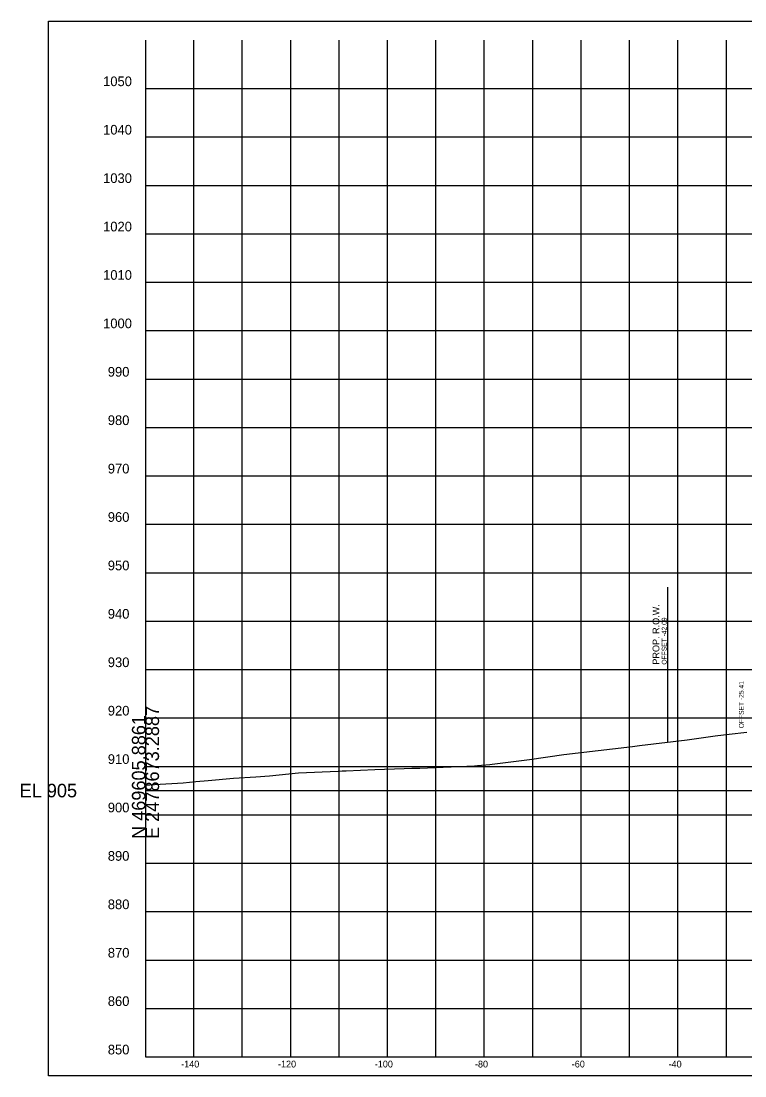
# Model space of a CAD drawing. Extents: x -26 to 2478923, y -10 to 469990.
# Drawn here: x -25.7 to 123.8, y 5941.1 to 6158.9 of the extents above; entities that cross this region are included whole.
import ezdxf

# ---------------------------------------------------------------- set-up
doc = ezdxf.new("R2010")
doc.units = 0
for name, color, linetype in [('DESIGN - ROW - Right-of-Way and Easement Labels', 7, 'Continuous'), ('DESIGN - ROW - Right-of-Way Linework', 7, 'Continuous'), ('DESIGN - SHEET - Corner Text', 7, 'Continuous'), ('DESIGN - SHEET - Light Grid', 7, 'Continuous'), ('DESIGN - SHEET - Linework', 7, 'Continuous'), ('DESIGN - SHEET - Plot Shape', 7, 'Continuous'), ('DESIGN - TYPICAL - Slope Tie Text', 7, 'Continuous'), ('SURVEY - GROUND - Top of Ground', 7, 'Continuous')]:
    doc.layers.add(name, color=color, linetype=linetype)

msp = doc.modelspace()

# ---------------------------------------------------------------- linework, layer by layer
at = {"layer": 'DESIGN - ROW - Right-of-Way Linework'}
msp.add_line((107.91, 6010.01), (107.91, 6042.01), dxfattribs=at)
at = {"layer": 'DESIGN - SHEET - Light Grid'}
msp.add_line((0, 6000), (150, 6000), dxfattribs=at)
at = {"layer": 'DESIGN - SHEET - Linework'}
for p, q in [((10, 5945), (10, 6155)), ((10, 5945), (10, 6155)), ((10, 5945), (10, 6155)), ((10, 5945), (10, 6155)), ((20, 5945), (20, 6155)), ((20, 5945), (20, 6155)), ((20, 5945), (20, 6155)), ((20, 5945), (20, 6155)), ((30, 5945), (30, 6155)), ((30, 5945), (30, 6155)), ((30, 5945), (30, 6155)), ((30, 5945), (30, 6155)), ((40, 5945), (40, 6155)), ((40, 5945), (40, 6155)), ((40, 5945), (40, 6155)), ((40, 5945), (40, 6155)), ((50, 5945), (50, 6155)), ((50, 5945), (50, 6155)), ((50, 5945), (50, 6155)), ((50, 5945), (50, 6155)), ((60, 5945), (60, 6155)), ((60, 5945), (60, 6155)), ((60, 5945), (60, 6155)), ((60, 5945), (60, 6155)), ((70, 5945), (70, 6155)), ((70, 5945), (70, 6155)), ((70, 5945), (70, 6155)), ((70, 5945), (70, 6155)), ((80, 5945), (80, 6155)), ((80, 5945), (80, 6155)), ((80, 5945), (80, 6155)), ((80, 5945), (80, 6155)), ((90, 5945), (90, 6155)), ((90, 5945), (90, 6155)), ((90, 5945), (90, 6155)), ((90, 5945), (90, 6155)), ((100, 5945), (100, 6155)), ((100, 5945), (100, 6155)), ((100, 5945), (100, 6155)), ((100, 5945), (100, 6155)), ((110, 5945), (110, 6155)), ((110, 5945), (110, 6155)), ((110, 5945), (110, 6155)), ((110, 5945), (110, 6155)), ((120, 5945), (120, 6155)), ((120, 5945), (120, 6155)), ((120, 5945), (120, 6155)), ((120, 5945), (120, 6155)), ((0, 6145), (300, 6145)), ((0, 6145), (300, 6145)), ((0, 6145), (300, 6145)), ((0, 6145), (300, 6145)), ((0, 6135), (300, 6135)), ((0, 6135), (300, 6135)), ((0, 6135), (300, 6135)), ((0, 6135), (300, 6135)), ((0, 6125), (300, 6125)), ((0, 6125), (300, 6125)), ((0, 6125), (300, 6125)), ((0, 6125), (300, 6125)), ((0, 6115), (300, 6115)), ((0, 6115), (300, 6115)), ((0, 6115), (300, 6115)), ((0, 6115), (300, 6115)), ((0, 6105), (300, 6105)), ((0, 6105), (300, 6105)), ((0, 6105), (300, 6105)), ((0, 6105), (300, 6105)), ((0, 6095), (300, 6095)), ((0, 6095), (300, 6095)), ((0, 6095), (300, 6095)), ((0, 6095), (300, 6095)), ((0, 6085), (300, 6085)), ((0, 6085), (300, 6085)), ((0, 6085), (300, 6085)), ((0, 6085), (300, 6085)), ((0, 6075), (300, 6075)), ((0, 6075), (300, 6075)), ((0, 6075), (300, 6075)), ((0, 6075), (300, 6075)), ((0, 6065), (300, 6065)), ((0, 6065), (300, 6065)), ((0, 6065), (300, 6065)), ((0, 6065), (300, 6065)), ((0, 6055), (300, 6055)), ((0, 6055), (300, 6055)), ((0, 6055), (300, 6055)), ((0, 6055), (300, 6055)), ((0, 6045), (300, 6045)), ((0, 6045), (300, 6045)), ((0, 6045), (300, 6045)), ((0, 6045), (300, 6045)), ((0, 6035), (300, 6035)), ((0, 6035), (300, 6035)), ((0, 6035), (300, 6035)), ((0, 6035), (300, 6035)), ((0, 6025), (300, 6025)), ((0, 6025), (300, 6025)), ((0, 6025), (300, 6025)), ((0, 6025), (300, 6025)), ((0, 6015), (300, 6015)), ((0, 6015), (300, 6015)), ((0, 6015), (300, 6015)), ((0, 6015), (300, 6015)), ((0, 6005), (300, 6005)), ((0, 6005), (300, 6005)), ((0, 6005), (300, 6005)), ((0, 6005), (300, 6005)), ((0, 5995), (300, 5995)), ((0, 5995), (300, 5995)), ((0, 5995), (300, 5995)), ((0, 5995), (300, 5995)), ((0, 5985), (300, 5985)), ((0, 5985), (300, 5985)), ((0, 5985), (300, 5985)), ((0, 5985), (300, 5985)), ((0, 5975), (300, 5975)), ((0, 5975), (300, 5975)), ((0, 5975), (300, 5975)), ((0, 5975), (300, 5975)), ((0, 5965), (300, 5965)), ((0, 5965), (300, 5965)), ((0, 5965), (300, 5965)), ((0, 5965), (300, 5965)), ((0, 5955), (300, 5955)), ((0, 5955), (300, 5955)), ((0, 5955), (300, 5955)), ((0, 5955), (300, 5955))]:
    msp.add_line(p, q, dxfattribs=at)
msp.add_lwpolyline([(0, 6155), (0, 5945), (300, 5945), (300, 6155)], dxfattribs=at)
msp.add_lwpolyline([(0, 6155), (0, 5945), (300, 5945), (300, 6155)], dxfattribs=at)
msp.add_lwpolyline([(0, 6155), (0, 5945), (300, 5945), (300, 6155)], dxfattribs=at)
msp.add_lwpolyline([(0, 6155), (0, 5945), (300, 5945), (300, 6155)], dxfattribs=at)
at = {"layer": 'DESIGN - SHEET - Plot Shape'}
msp.add_lwpolyline([(-20, 6158.94), (320, 6158.94), (320, 5941.06), (-20, 5941.06)], close=True, dxfattribs=at)
msp.add_lwpolyline([(-20, 6158.94), (320, 6158.94), (320, 5941.06), (-20, 5941.06)], close=True, dxfattribs=at)
msp.add_lwpolyline([(-20, 6158.94), (320, 6158.94), (320, 5941.06), (-20, 5941.06)], close=True, dxfattribs=at)
msp.add_lwpolyline([(-20, 6158.94), (320, 6158.94), (320, 5941.06), (-20, 5941.06)], close=True, dxfattribs=at)
at = {"layer": 'SURVEY - GROUND - Top of Ground'}
msp.add_lwpolyline([(0, 6001.09), (1.85, 6001.23), (7.78, 6001.61), (10.41, 6001.88), (12.95, 6002.05), (18.2, 6002.55), (22.78, 6002.81), (25.64, 6003.03), (31.6, 6003.66), (39.78, 6004), (40.66, 6004.05), (41.44, 6004.05), (47.38, 6004.35), (53.43, 6004.56), (55.02, 6004.63), (56.71, 6004.64), (67.96, 6005.13), (68.58, 6005.2), (71.17, 6005.38), (71.64, 6005.42), (79.32, 6006.4), (86.44, 6007.46), (89.39, 6007.81), (100.58, 6009.1), (101.11, 6009.17), (102.04, 6009.29), (111.9, 6010.51), (117.71, 6011.32), (120.57, 6011.65), (124.24, 6012.06)], dxfattribs=at)

# ---------------------------------------------------------------- texts
at = {"layer": 'DESIGN - ROW - Right-of-Way and Easement Labels'}
for s, height, p in [('PROP. R.O.W.', 1.4, (106.16, 6026.01)), ('OFFSET -42.09', 1, (107.66, 6026.01))]:
    msp.add_text(s, height=height, rotation=90, dxfattribs=at).set_placement(p)
at = {"layer": 'DESIGN - SHEET - Corner Text'}
for s, height, p in [('1050', 2, (-8.75, 6145.5)), ('1050', 2, (-8.75, 6145.5)), ('1050', 2, (-8.75, 6145.5)), ('1050', 2, (-8.75, 6145.5)), ('1040', 2, (-8.75, 6135.5)), ('1040', 2, (-8.75, 6135.5)), ('1040', 2, (-8.75, 6135.5)), ('1040', 2, (-8.75, 6135.5)), ('1030', 2, (-8.75, 6125.5)), ('1030', 2, (-8.75, 6125.5)), ('1030', 2, (-8.75, 6125.5)), ('1030', 2, (-8.75, 6125.5)), ('1020', 2, (-8.75, 6115.5)), ('1020', 2, (-8.75, 6115.5)), ('1020', 2, (-8.75, 6115.5)), ('1020', 2, (-8.75, 6115.5)), ('1010', 2, (-8.75, 6105.5)), ('1010', 2, (-8.75, 6105.5)), ('1010', 2, (-8.75, 6105.5)), ('1010', 2, (-8.75, 6105.5)), ('1000', 2, (-8.75, 6095.5)), ('1000', 2, (-8.75, 6095.5)), ('1000', 2, (-8.75, 6095.5)), ('1000', 2, (-8.75, 6095.5)), ('990', 2, (-7.78, 6085.5)), ('990', 2, (-7.78, 6085.5)), ('990', 2, (-7.78, 6085.5)), ('990', 2, (-7.78, 6085.5)), ('980', 2, (-7.78, 6075.5)), ('980', 2, (-7.78, 6075.5)), ('980', 2, (-7.78, 6075.5)), ('980', 2, (-7.78, 6075.5)), ('970', 2, (-7.78, 6065.5)), ('970', 2, (-7.78, 6065.5)), ('970', 2, (-7.78, 6065.5)), ('970', 2, (-7.78, 6065.5)), ('960', 2, (-7.78, 6055.5)), ('960', 2, (-7.78, 6055.5)), ('960', 2, (-7.78, 6055.5)), ('960', 2, (-7.78, 6055.5)), ('950', 2, (-7.78, 6045.5)), ('950', 2, (-7.78, 6045.5)), ('950', 2, (-7.78, 6045.5)), ('950', 2, (-7.78, 6045.5)), ('940', 2, (-7.78, 6035.5)), ('940', 2, (-7.78, 6035.5)), ('940', 2, (-7.78, 6035.5)), ('940', 2, (-7.78, 6035.5)), ('930', 2, (-7.78, 6025.5)), ('930', 2, (-7.78, 6025.5)), ('930', 2, (-7.78, 6025.5)), ('930', 2, (-7.78, 6025.5)), ('920', 2, (-7.78, 6015.5)), ('920', 2, (-7.78, 6015.5)), ('920', 2, (-7.78, 6015.5)), ('920', 2, (-7.78, 6015.5)), ('910', 2, (-7.78, 6005.5)), ('910', 2, (-7.78, 6005.5)), ('910', 2, (-7.78, 6005.5)), ('910', 2, (-7.78, 6005.5)), ('900', 2, (-7.78, 5995.5)), ('900', 2, (-7.78, 5995.5)), ('900', 2, (-7.78, 5995.5)), ('900', 2, (-7.78, 5995.5)), ('890', 2, (-7.78, 5985.5)), ('890', 2, (-7.78, 5985.5)), ('890', 2, (-7.78, 5985.5)), ('890', 2, (-7.78, 5985.5)), ('880', 2, (-7.78, 5975.5)), ('880', 2, (-7.78, 5975.5)), ('880', 2, (-7.78, 5975.5)), ('880', 2, (-7.78, 5975.5)), ('870', 2, (-7.78, 5965.5)), ('870', 2, (-7.78, 5965.5)), ('870', 2, (-7.78, 5965.5)), ('870', 2, (-7.78, 5965.5)), ('860', 2, (-7.78, 5955.5)), ('860', 2, (-7.78, 5955.5)), ('860', 2, (-7.78, 5955.5)), ('860', 2, (-7.78, 5955.5)), ('850', 2, (-7.78, 5945.5)), ('850', 2, (-7.78, 5945.5)), ('850', 2, (-7.78, 5945.5)), ('850', 2, (-7.78, 5945.5)), ('-140', 1.4, (7.37, 5942.8)), ('-140', 1.4, (7.37, 5942.8)), ('-140', 1.4, (7.37, 5942.8)), ('-140', 1.4, (7.37, 5942.8)), ('-120', 1.4, (27.37, 5942.8)), ('-120', 1.4, (27.37, 5942.8)), ('-120', 1.4, (27.37, 5942.8)), ('-120', 1.4, (27.37, 5942.8)), ('-100', 1.4, (47.37, 5942.8)), ('-100', 1.4, (47.37, 5942.8)), ('-100', 1.4, (47.37, 5942.8)), ('-100', 1.4, (47.37, 5942.8)), ('-80', 1.4, (68.06, 5942.8)), ('-80', 1.4, (68.06, 5942.8)), ('-80', 1.4, (68.06, 5942.8)), ('-80', 1.4, (68.06, 5942.8)), ('-60', 1.4, (88.06, 5942.8)), ('-60', 1.4, (88.06, 5942.8)), ('-60', 1.4, (88.06, 5942.8)), ('-60', 1.4, (88.06, 5942.8)), ('-40', 1.4, (108.06, 5942.8)), ('-40', 1.4, (108.06, 5942.8)), ('-40', 1.4, (108.06, 5942.8)), ('-40', 1.4, (108.06, 5942.8))]:
    msp.add_text(s, height=height, dxfattribs=at).set_placement(p)
at = {"layer": 'DESIGN - SHEET - Light Grid'}
for s, p in [('E 2478673.2887', (2.8, 5990)), ('N 469605.8861', (0, 5990))]:
    msp.add_text(s, height=2.8, rotation=90, dxfattribs=at).set_placement(p)
msp.add_text('EL 905', height=2.8, dxfattribs=at).set_placement((-26, 5998.6))
at = {"layer": 'DESIGN - TYPICAL - Slope Tie Text'}
msp.add_text('OFFSET -25.41', height=1, rotation=90, dxfattribs=at).set_placement((123.59, 6012.86))

doc.saveas('drawing.dxf')
